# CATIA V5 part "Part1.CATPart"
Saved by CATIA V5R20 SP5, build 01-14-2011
Part number: Part1
Bounding box of the stored display mesh (mm): x -40 to 40, y -20 to 20, z 0 to 80
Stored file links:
  C:\Users\wcz0113\Desktop\Part1.CATPart
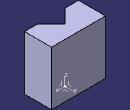
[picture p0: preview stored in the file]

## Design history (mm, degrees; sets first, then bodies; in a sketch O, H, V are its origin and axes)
AxisSystem1: origin (0, 0, 0), X (1, 0, 0), Y (0, 1, 0), Z (0, 0, 1)
Body1 (main body)
  Sketch1 on xy-plane, origin (0, 0, 0), H (1, 0, 0), V (0, 1, 0)
    line L1 (40, 20) -> (-40, 20)
    line L2 (-40, 20) -> (-40, -20)
    line L3 (-40, -20) -> (-20, -20)
    line L4 (-20, -20) -> (0, 0)
    point P5 (0, 0)
    line L5 (0, 0) -> (20, -20)
    point P6 (20, -20)
    line L6 (20, -20) -> (40, -20)
    line L7 (40, -20) -> (40, 20)
    reference projected line E1 through (0, 0) direction (0, 1) from edge [YZ plane of AxisSystem1 | XY plane of AxisSystem1]
    reference projected line E2 through (0, 0) direction (0, 1) from edge [YZ plane of AxisSystem1 | XY plane of AxisSystem1]
    reference projected line E3 through (0, 0) direction (1, 0) from edge [XY plane of AxisSystem1 | ZX plane of AxisSystem1]
    distance E3 L1 = 20
    distance L1 L3 = 40
    angle L4 L5 = 90
    distance L2 L7 = 80
    horizontal: L1 H, L3 H, L6 H
    vertical: L2 V, L7 V
    coincidence: P5 V, P5 H, P6 L3
    symmetry: L7 L2 E1, L4 L5 E2
  Pad1: profile Sketch1, direction (0, 0, 1), length 80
